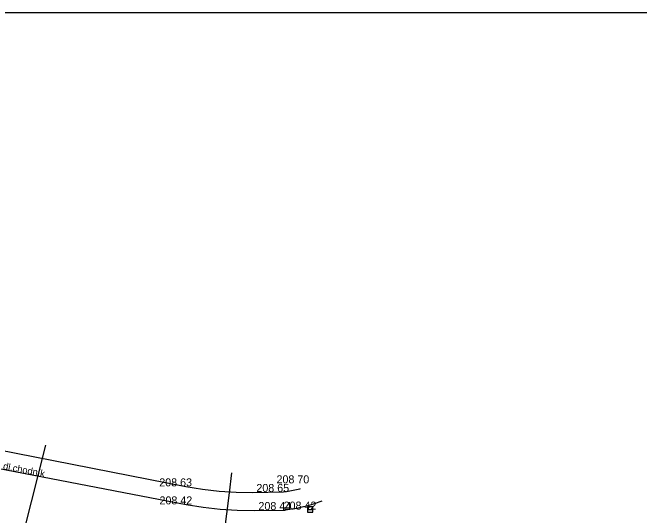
# Model space of a CAD drawing. Extents: x -524633 to -524336, y -1187893 to -1187683.
# Drawn here: x -524520 to -524461.3, y -1187729.8 to -1187682.7 of the extents above; entities that cross this region are included whole.
import ezdxf

# ---------------------------------------------------------------- set-up
doc = ezdxf.new("R2010")
doc.units = 0
for name, color, linetype in [('Vrstva 1', 7, 'Continuous'), ('Vrstva 10', 7, 'Continuous'), ('Vrstva 11', 7, 'Continuous'), ('Vrstva 27', 7, 'Continuous'), ('Vrstva 3', 7, 'Continuous'), ('Vrstva 4', 7, 'Continuous'), ('Vrstva 40', 7, 'Continuous'), ('Vrstva 53', 7, 'Continuous'), ('Vrstva 55', 7, 'Continuous'), ('Vrstva 63', 7, 'Continuous')]:
    doc.layers.add(name, color=color, linetype=linetype)

msp = doc.modelspace()

# ---------------------------------------------------------------- linework, layer by layer
at = {"layer": 'Vrstva 1'}
for p, q in [((-524503.74, -1187727.08), (-524503.74, -1187727.08)), ((-524494.643, -1187727.602), (-524494.643, -1187727.602)), ((-524494.32, -1187727.15), (-524494.32, -1187727.15)), ((-524503.72, -1187728.77), (-524503.72, -1187728.77)), ((-524494.449, -1187729.299), (-524494.449, -1187729.299)), ((-524492.24, -1187729.28), (-524492.24, -1187729.28)), ((-524492.092, -1187729.257), (-524492.092, -1187729.257)), ((-524491.7, -1187728.8), (-524491.7, -1187728.8))]:
    msp.add_line(p, q, dxfattribs=at)
at = {"layer": 'Vrstva 10'}
msp.add_line((-524530.02, -1187723.71), (-524503.72, -1187728.77), dxfattribs=at)
msp.add_lwpolyline([(-524503.72, -1187728.77), (-524502.14, -1187729.03), (-524500.54, -1187729.22), (-524498.94, -1187729.32), (-524497.33, -1187729.35), (-524494.449, -1187729.299)], dxfattribs=at)
at = {"layer": 'Vrstva 11'}
msp.add_line((-524532.8, -1187721.4), (-524503.74, -1187727.08), dxfattribs=at)
for points in [[(-524503.74, -1187727.08), (-524502.19, -1187727.34), (-524500.62, -1187727.53), (-524499.05, -1187727.63), (-524497.47, -1187727.66), (-524494.644, -1187727.603)], [(-524494.644, -1187727.603), (-524494.592, -1187727.602), (-524494.327, -1187727.559), (-524494.012, -1187727.508), (-524493.697, -1187727.45), (-524493.385, -1187727.383), (-524493.074, -1187727.308), (-524493.007, -1187727.29)], [(-524491.017, -1187728.473), (-524491.283, -1187728.571), (-524491.601, -1187728.68), (-524491.922, -1187728.781), (-524492.245, -1187728.875), (-524492.57, -1187728.96), (-524492.896, -1187729.038), (-524493.225, -1187729.108), (-524493.555, -1187729.171), (-524493.887, -1187729.225), (-524494.22, -1187729.272), (-524494.412, -1187729.299), (-524494.449, -1187729.299)]]:
    msp.add_lwpolyline(points, dxfattribs=at)
at = {"layer": 'Vrstva 27'}
msp.add_line((-524492.342, -1187729.257), (-524491.842, -1187729.257), dxfattribs=at)
msp.add_lwpolyline([(-524492.342, -1187729.507), (-524491.842, -1187729.507), (-524491.842, -1187729.007), (-524492.342, -1187729.007)], close=True, dxfattribs=at)
at = {"layer": 'Vrstva 53'}
msp.add_lwpolyline([(-524499.468, -1187725.8), (-524499.705, -1187727.675), (-524499.956, -1187729.659), (-524500.547, -1187734.331), (-524501.236, -1187739.779), (-524502.2, -1187746.29)], dxfattribs=at)
at = {"layer": 'Vrstva 55'}
msp.add_line((-524516.896, -1187723.213), (-524522.885, -1187746.999), dxfattribs=at)
at = {"layer": 'Vrstva 63'}
msp.add_lwpolyline([(-524632.797, -1187892.658), (-524632.797, -1187682.658), (-524335.797, -1187682.658), (-524335.797, -1187892.658)], close=True, dxfattribs=at)

# ---------------------------------------------------------------- texts
at = {"layer": 'Vrstva 3'}
for s, p in [('208 63 ', (-524506.24, -1187727.08)), ('208 70 ', (-524495.258, -1187726.796)), ('208 42 ', (-524506.22, -1187728.77))]:
    msp.add_text(s, height=0.75, dxfattribs=at).set_placement(p)
at = {"layer": 'Vrstva 4'}
for s, p in [('208 65 ', (-524497.143, -1187727.602)), ('208 44 ', (-524496.949, -1187729.299)), ('208 42 ', (-524494.592, -1187729.257))]:
    msp.add_text(s, height=0.75, dxfattribs=at).set_placement(p)
at = {"layer": 'Vrstva 40'}
msp.add_text('dl.chodník', height=0.65, rotation=349.15722, dxfattribs=at).set_placement((-524520.909, -1187725.473))

doc.saveas('drawing.dxf')
